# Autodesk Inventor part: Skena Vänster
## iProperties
Author: Tobben
Created: 2001-12
Part Number: Skena Vänster
Material: S235JRG2
Document SubType Name: Modeling
Designer: Tobben
Control State: 0
Master: False
Checked Out: False
PropertySet Name: Design Tracking Control
Shininess: 64.0
Angle Display Precision: 2
Document Length Units: 11269
Document Angle Units: 11283
Document Time Units: 11279
Document Mass Units: 11290
Document Length Units Precision: 3
Document Angle Units Precision: 2
Compacted: False
PropertySet Name: _Private Model Information
Density: 0.0
Volumn: 0.0
Area: 0.0
PropertySet Name: Model Information
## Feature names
1. Extrusion1
2. Hole1
3. Rectangular Pattern1
4. Hole2
5. Extrusion3
6. Extrusion4
